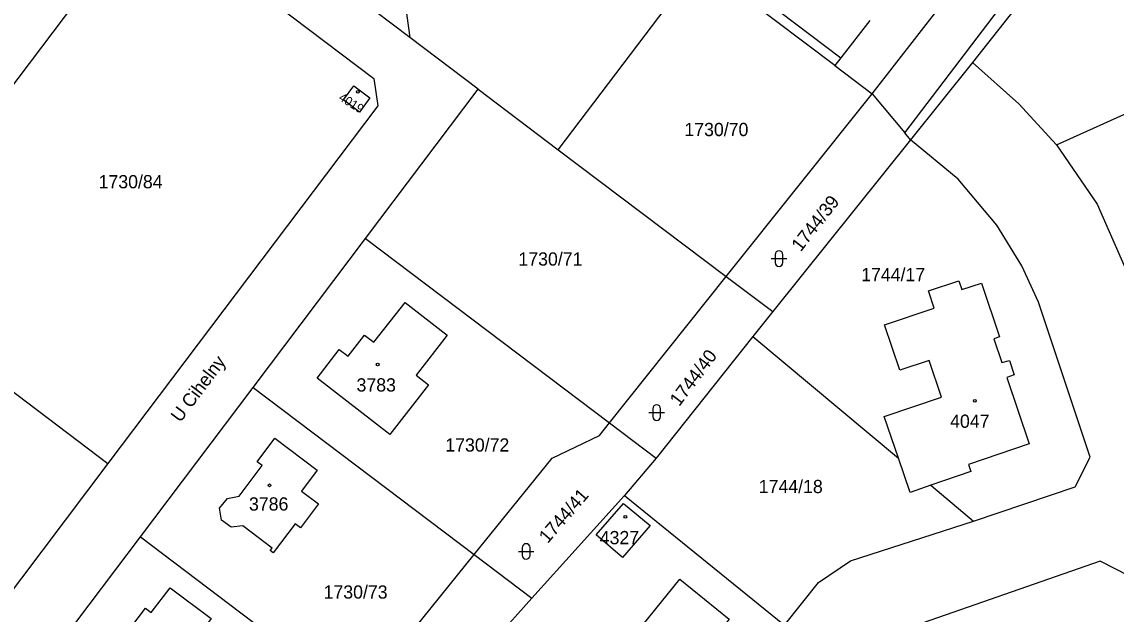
# Model space of a CAD drawing. Extents: x -679220 to -673243, y -1075091 to -1066557.
# Drawn here: x -677014 to -676873.4, y -1072401 to -1072325 of the extents above; entities that cross this region are included whole.
import ezdxf

# ---------------------------------------------------------------- set-up
doc = ezdxf.new("R2010")
doc.units = 0
for name, color, linetype in [('Hranice parcel', 7, 'Continuous'), ('Parcelní čísla', 7, 'Continuous'), ('Pop  PČ popisy', 7, 'Continuous'), ('Značky budov', 7, 'Continuous'), ('Značky kultur', 7, 'Continuous')]:
    doc.layers.add(name, color=color, linetype=linetype)

msp = doc.modelspace()

# ---------------------------------------------------------------- linework, layer by layer
at = {"layer": 'Hranice parcel'}
for p, q in [((-676869.87, -1072302.33), (-676891.88, -1072330.24)), ((-676964.12, -1072327.04), (-676979.28, -1072315.59)), ((-676945.08, -1072341.44), (-676926.98, -1072317.5)), ((-676909.57, -1072330.65), (-676926.98, -1072317.5)), ((-676905.06, -1072324.86), (-676908.8, -1072329.65)), ((-676955.34, -1072333.67), (-676964.12, -1072327.04)), ((-676881.09, -1072340.82), (-676850.38, -1072326.91)), ((-676908.8, -1072329.65), (-676909.57, -1072330.65)), ((-676891.88, -1072330.24), (-676899.84, -1072340.16)), ((-676909.57, -1072330.65), (-676904.77, -1072334.29)), ((-676969.81, -1072352.82), (-676955.34, -1072333.67)), ((-676955.34, -1072333.67), (-676945.08, -1072341.44)), ((-676923.5, -1072357.73), (-676904.77, -1072334.29)), ((-676904.77, -1072334.29), (-676900.59, -1072339.27)), ((-676899.84, -1072340.16), (-676917.54, -1072362.22)), ((-676899.84, -1072340.16), (-676900.59, -1072339.27)), ((-676945.08, -1072341.44), (-676923.5, -1072357.73)), ((-676984.27, -1072371.97), (-676969.81, -1072352.82)), ((-676969.81, -1072352.82), (-676938.49, -1072376.48)), ((-677034.04, -1072358.2), (-677002.92, -1072381.7)), ((-676938.49, -1072376.48), (-676923.5, -1072357.73)), ((-676923.5, -1072357.73), (-676917.54, -1072362.22)), ((-676917.54, -1072362.22), (-676920.09, -1072365.43)), ((-676920.09, -1072365.43), (-676932.51, -1072381.04)), ((-676920.09, -1072365.43), (-676901.39, -1072381.05)), ((-676998.74, -1072391.12), (-676984.27, -1072371.97)), ((-676984.27, -1072371.97), (-676955.89, -1072393.41)), ((-676938.49, -1072376.48), (-676932.51, -1072381.04)), ((-676932.51, -1072381.04), (-676936.55, -1072385.82)), ((-676897.25, -1072384.51), (-676891.76, -1072389.1)), ((-676936.55, -1072385.82), (-676948.47, -1072399.01)), ((-676936.55, -1072385.82), (-676916.03, -1072402.47)), ((-677013.21, -1072410.27), (-676998.74, -1072391.12)), ((-676998.74, -1072391.12), (-676971, -1072412.08)), ((-676971, -1072412.08), (-676955.89, -1072393.41)), ((-676955.89, -1072393.41), (-676948.47, -1072399.01)), ((-676948.47, -1072399.01), (-676958.94, -1072410.64))]:
    msp.add_line(p, q, dxfattribs=at)
for points in [[(-676904.77, -1072334.29), (-676870.34, -1072290.1), (-676818.72, -1072215.8), (-676800.09, -1072189.36)], [(-676900.59, -1072339.27), (-676865.59, -1072293.33), (-676821.22, -1072232.97)], [(-676950.18, -1072299.98), (-676949.27, -1072299.96), (-676948.29, -1072300.16), (-676947.39, -1072300.57), (-676945.74, -1072301.71), (-676908.8, -1072329.65)], [(-676946.01, -1072303.12), (-676951.64, -1072303.88), (-676964.9, -1072321.44), (-676964.12, -1072327.04)], [(-677034.04, -1072358.2), (-676999.38, -1072312.31), (-676995.87, -1072311.82), (-676968.74, -1072332.31), (-676968.26, -1072335.81), (-677002.92, -1072381.7)], [(-676891.88, -1072330.24), (-676885.92, -1072335.57), (-676881.09, -1072340.82)], [(-676971.34, -1072333.24), (-676969.29, -1072334.79), (-676970.62, -1072336.61), (-676972.67, -1072335.03), (-676971.34, -1072333.24)], [(-676891.76, -1072389.1), (-676878.69, -1072384.73), (-676876.78, -1072380.9), (-676883.43, -1072361.01), (-676885.57, -1072356.35), (-676888.78, -1072351.13), (-676893.71, -1072345.23), (-676899.84, -1072340.16)], [(-676881.09, -1072340.82), (-676875.87, -1072348.42), (-676872.01, -1072357.2), (-676871.02, -1072360.14)], [(-677002.92, -1072381.7), (-677016.78, -1072400.05), (-677022.38, -1072400.83), (-677047.12, -1072382.15), (-677047.9, -1072376.55), (-677034.04, -1072358.2)], [(-676901.39, -1072381.05), (-676903.21, -1072375.69), (-676895.85, -1072373.21), (-676897.45, -1072368.5), (-676901.21, -1072369.76), (-676903.19, -1072363.93), (-676896.82, -1072361.77), (-676897.55, -1072359.57), (-676893.65, -1072358.28), (-676893.27, -1072359.4), (-676890.72, -1072358.59), (-676888.4, -1072365.45), (-676889.15, -1072365.71), (-676888.11, -1072368.77), (-676887.15, -1072368.51), (-676886.54, -1072370.34), (-676887.49, -1072370.67), (-676884.61, -1072379.2), (-676892.4, -1072381.84), (-676892.11, -1072382.76), (-676897.25, -1072384.51)], [(-676964.75, -1072361.04), (-676959.34, -1072365.25), (-676963.31, -1072370.37), (-676961.75, -1072371.61), (-676966.72, -1072378), (-676976.05, -1072370.76), (-676973.21, -1072367.09), (-676972.07, -1072367.96), (-676969.94, -1072365.25), (-676968.75, -1072366.15), (-676964.75, -1072361.04)], [(-676955.89, -1072393.41), (-676945.88, -1072381.03), (-676939.79, -1072378.11), (-676938.49, -1072376.48)], [(-676987.07, -1072389.9), (-676988.3, -1072388.98), (-676988.57, -1072387.45), (-676987.56, -1072386.19), (-676986.07, -1072385.93), (-676983.1, -1072381.96), (-676983.73, -1072381.5), (-676981.45, -1072378.47), (-676976.02, -1072382.57), (-676978.03, -1072385.25), (-676975.86, -1072386.91), (-676978.19, -1072389.96), (-676978.88, -1072389.45), (-676981.67, -1072393.18), (-676982.07, -1072392.9), (-676981.81, -1072392.59), (-676985.59, -1072389.73), (-676987.07, -1072389.9)], [(-676897.25, -1072384.51), (-676899.91, -1072385.42), (-676901.39, -1072381.05)], [(-676933.29, -1072389.68), (-676936.82, -1072393.8), (-676940.2, -1072390.86), (-676936.7, -1072386.85), (-676933.29, -1072389.68)], [(-676916.03, -1072402.47), (-676911.66, -1072396.99), (-676907.56, -1072394.23), (-676891.76, -1072389.1)], [(-676865.11, -1072416.25), (-676871.72, -1072396.17), (-676875.51, -1072394.24), (-676901.03, -1072403.13)], [(-676923.13, -1072401.7), (-676931.78, -1072412.45), (-676938.15, -1072407.32), (-676929.48, -1072396.56), (-676923.13, -1072401.7)], [(-677003.97, -1072408.09), (-676998.08, -1072400.28), (-676997.34, -1072400.82), (-676994.91, -1072397.66), (-676989.63, -1072401.63), (-676992.03, -1072404.84), (-676991.27, -1072405.43), (-676997.16, -1072413.21), (-677003.97, -1072408.09)]]:
    msp.add_lwpolyline(points, dxfattribs=at)
at = {"layer": 'Značky budov'}
for centre in [(-676970.81, -1072334.03), (-676968.27, -1072369.01), (-676891.57, -1072373.68), (-676982.17, -1072384.52), (-676936.46, -1072388.57)]:
    msp.add_circle(centre, 0.175, dxfattribs=at)
at = {"layer": 'Značky kultur'}
for p, q in [((-676917.73, -1072355.42), (-676915.73, -1072355.42)), ((-676917.23, -1072354.92), (-676917.23, -1072355.92)), ((-676916.23, -1072355.92), (-676916.23, -1072354.92)), ((-676933.44, -1072375.19), (-676931.44, -1072375.19)), ((-676932.94, -1072374.69), (-676932.94, -1072375.69)), ((-676931.94, -1072375.69), (-676931.94, -1072374.69)), ((-676950.2, -1072393.01), (-676948.2, -1072393.01)), ((-676949.7, -1072392.51), (-676949.7, -1072393.51)), ((-676948.7, -1072393.51), (-676948.7, -1072392.51))]:
    msp.add_line(p, q, dxfattribs=at)
for centre, start, end in [((-676916.73, -1072354.92), 0, 180), ((-676916.73, -1072355.92), 180, 359.9879), ((-676932.44, -1072374.69), 0, 180), ((-676932.44, -1072375.69), 180, 359.9879), ((-676949.2, -1072392.51), 0, 180), ((-676949.2, -1072393.51), 180, 359.9879)]:
    msp.add_arc(centre, 0.5, start, end, dxfattribs=at)

# ---------------------------------------------------------------- texts
at = {"layer": 'Parcelní čísla'}
for s, height, rotation, p in [('4019', 1.14, 328, (-676973.38, -1072335.02)), ('1744/39', 1.7, 52, (-676913.94, -1072354.63)), ('1744/40', 1.7, 53, (-676929.54, -1072374.48)), ('1744/41', 1.7, 49, (-676946.44, -1072392.06))]:
    msp.add_text(s, height=height, rotation=rotation, dxfattribs=at).set_placement(p)
for s, p in [('1730/70', (-676928.88, -1072339.7)), ('1730/84', (-677004.1, -1072346.4)), ('1730/71', (-676950.19, -1072356.32)), ('1744/17', (-676906.18, -1072358.33)), ('3783', (-676970.98, -1072372.48)), ('4047', (-676894.76, -1072377.14)), ('1730/72', (-676959.58, -1072380.19)), ('1744/18', (-676919.33, -1072385.52)), ('3786', (-676984.79, -1072387.76)), ('4327', (-676939.75, -1072392.08)), ('1730/73', (-676975.21, -1072399.06))]:
    msp.add_text(s, height=1.7, dxfattribs=at).set_placement(p)
at = {"layer": 'Pop  PČ popisy'}
msp.add_text('U Cihelny', height=1.7, rotation=53, dxfattribs=at).set_placement((-676993.61, -1072376.55))

doc.saveas('drawing.dxf')
